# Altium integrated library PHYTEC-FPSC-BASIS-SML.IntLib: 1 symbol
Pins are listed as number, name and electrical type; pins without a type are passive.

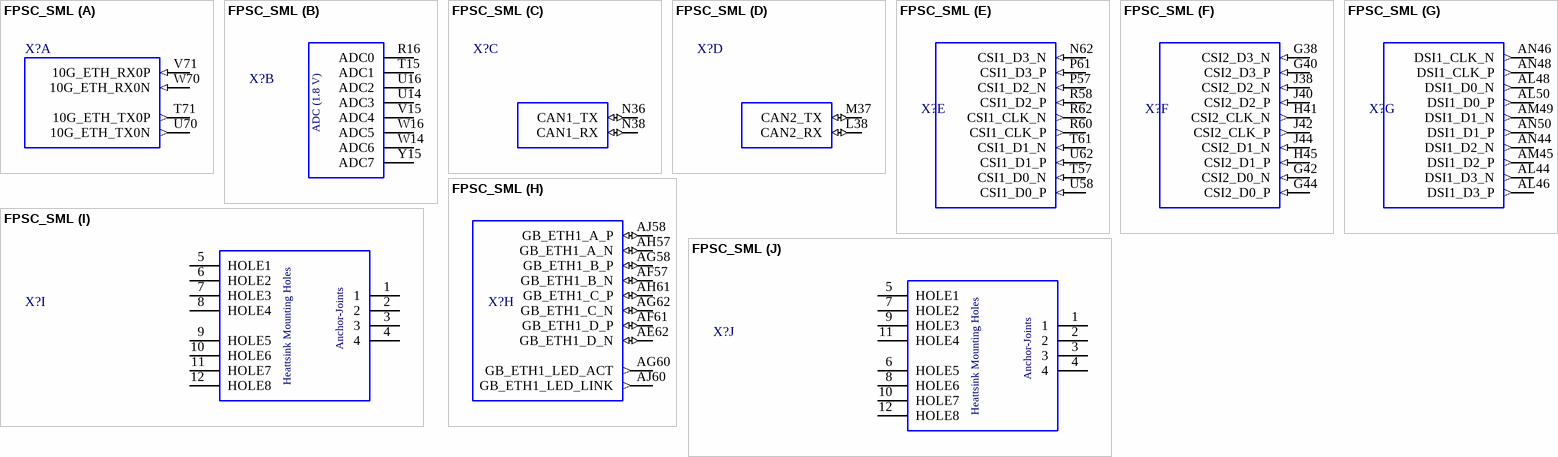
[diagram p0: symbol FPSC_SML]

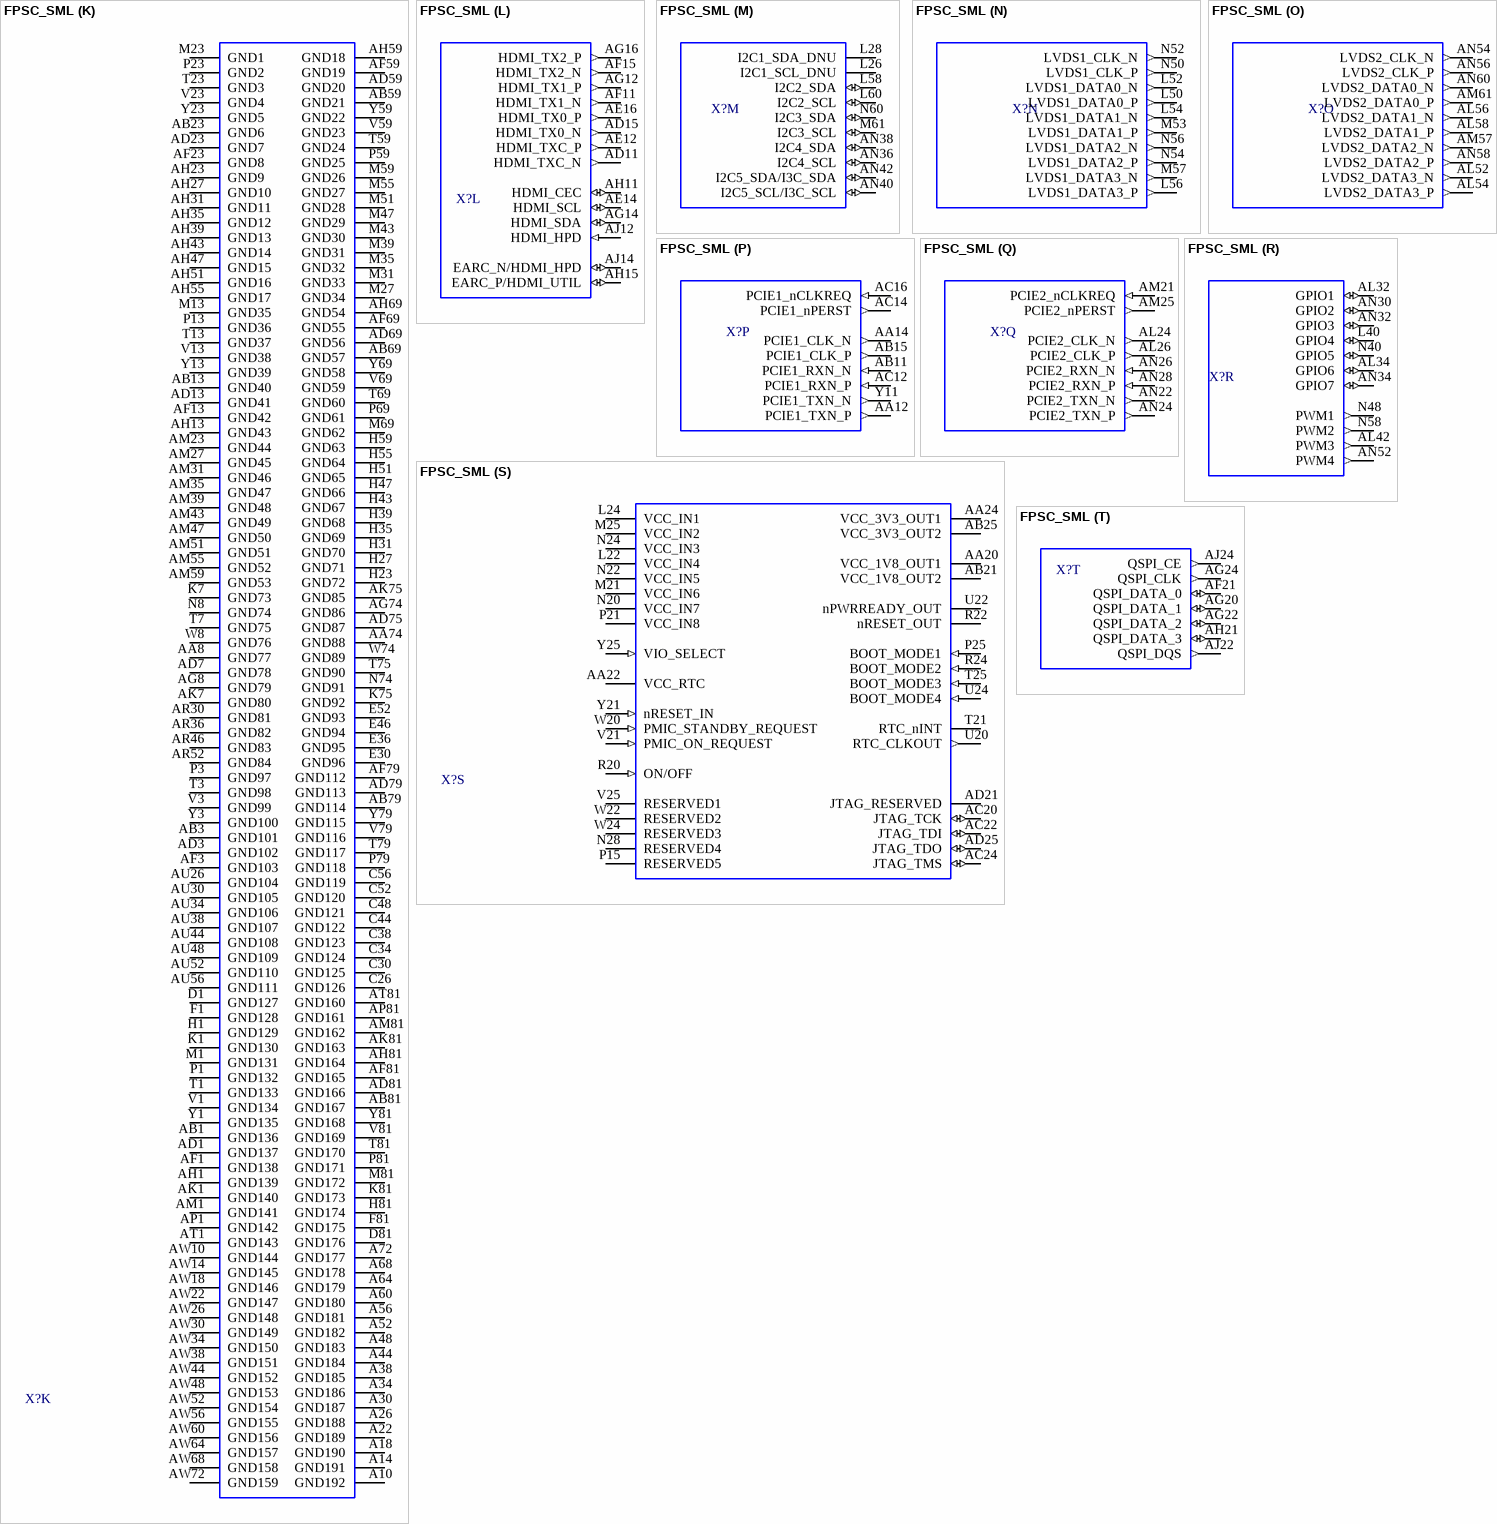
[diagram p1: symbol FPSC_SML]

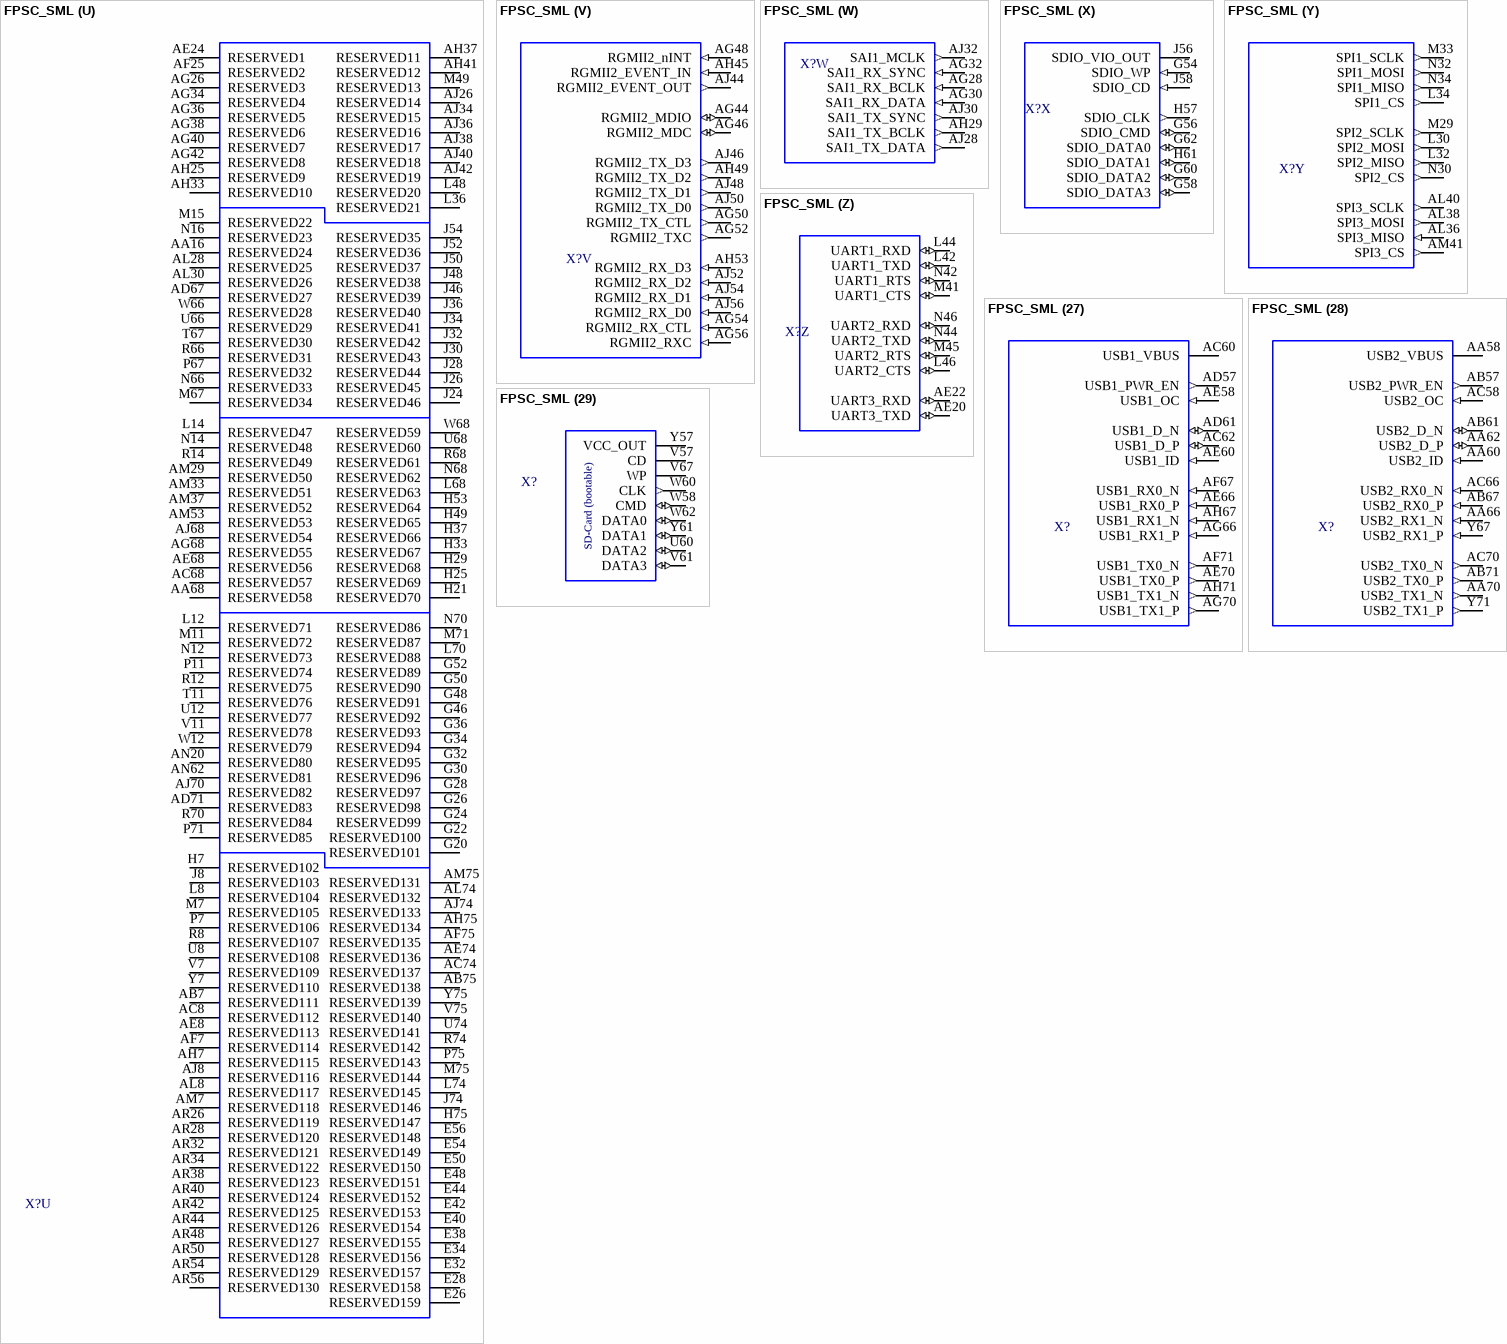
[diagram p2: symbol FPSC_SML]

## FPSC_SML
designator X?
footprint PHYTEC-FPSC-BASIS-SML (FPSC Basis für alle Varianten S,M und L)
part A pins: T71 10G_ETH_TX0P (out), U70 10G_ETH_TX0N (out), V71 10G_ETH_RX0P (in), W70 10G_ETH_RX0N (in)
part B pins: R16 ADC0, T15 ADC1, U14 ADC3, U16 ADC2, V15 ADC4, W14 ADC6, W16 ADC5, Y15 ADC7
part C pins: N36 CAN1_TX (io), N38 CAN1_RX (io)
part D pins: L38 CAN2_RX (io), M37 CAN2_TX (io)
part E pins: N62 CSI1_D3_N (in), P57 CSI1_D2_N (in), P61 CSI1_D3_P (in), R58 CSI1_D2_P (in), R60 CSI1_CLK_P (out), R62 CSI1_CLK_N (out), T57 CSI1_D0_N (in), T61 CSI1_D1_N (in), U58 CSI1_D0_P (in), U62 CSI1_D1_P (in)
part F pins: G38 CSI2_D3_N (in), G40 CSI2_D3_P (in), G42 CSI2_D0_N (in), G44 CSI2_D0_P (in), H41 CSI2_CLK_N (out), H45 CSI2_D1_P (in), J38 CSI2_D2_N (in), J40 CSI2_D2_P (in), J42 CSI2_CLK_P (out), J44 CSI2_D1_N (in)
part G pins: AL44 DSI1_D3_N (out), AL46 DSI1_D3_P (out), AL48 DSI1_D0_N (out), AL50 DSI1_D0_P (out), AM45 DSI1_D2_P (out), AM49 DSI1_D1_N (out), AN44 DSI1_D2_N (out), AN46 DSI1_CLK_N (out), AN48 DSI1_CLK_P (out), AN50 DSI1_D1_P (out)
part H pins: AE62 GB_ETH1_D_N (io), AF57 GB_ETH1_B_N (io), AF61 GB_ETH1_D_P (io), AG58 GB_ETH1_B_P (io), AG60 GB_ETH1_LED_ACT (out), AG62 GB_ETH1_C_N (io), AH57 GB_ETH1_A_N (io), AH61 GB_ETH1_C_P (io), AJ58 GB_ETH1_A_P (io), AJ60 GB_ETH1_LED_LINK (out)
part I pins: 1 (power), 2 (power), 3 (power), 4 (power), 5 HOLE1 (power), 6 HOLE2 (power), 7 HOLE3 (power), 8 HOLE4 (power), 9 HOLE5 (power), 10 HOLE6 (power), 11 HOLE7 (power), 12 HOLE8 (power)
part J pins: 1 (power), 2 (power), 3 (power), 4 (power), 5 HOLE1 (power), 6 HOLE5 (power), 7 HOLE2 (power), 8 HOLE6 (power), 9 HOLE3 (power), 10 HOLE7 (power), 11 HOLE4 (power), 12 HOLE8 (power)
part K pins: A10 GND192 (power), A14 GND191 (power), A18 GND190 (power), A22 GND189 (power), A26 GND188 (power), A30 GND187 (power), A34 GND186 (power), A38 GND185 (power), A44 GND184 (power), A48 GND183 (power), A52 GND182 (power), A56 GND181 (power), A60 GND180 (power), A64 GND179 (power), A68 GND178 (power), A72 GND177 (power), AA8 GND77 (power), AA74 GND88 (power), AB1 GND136 (power), AB3 GND101 (power), AB13 GND40 (power), AB23 GND6 (power), AB59 GND21 (power), AB69 GND57 (power), AB79 GND114 (power), AB81 GND167 (power), AD1 GND137 (power), AD3 GND102 (power), AD7 GND78 (power), AD13 GND41 (power), AD23 GND7 (power), AD59 GND20 (power), AD69 GND56 (power), AD75 GND87 (power), AD79 GND113 (power), AD81 GND166 (power), AF1 GND138 (power), AF3 GND103 (power), AF13 GND42 (power), AF23 GND8 (power), AF59 GND19 (power), AF69 GND55 (power), AF79 GND112 (power), AF81 GND165 (power), AG8 GND79 (power), AG74 GND86 (power), AH1 GND139 (power), AH13 GND43 (power), AH23 GND9 (power), AH27 GND10 (power), AH31 GND11 (power), AH35 GND12 (power), AH39 GND13 (power), AH43 GND14 (power), AH47 GND15 (power), AH51 GND16 (power), AH55 GND17 (power), AH59 GND18 (power), AH69 GND54 (power), AH81 GND164 (power), AK1 GND140 (power), AK7 GND80 (power), AK75 GND85 (power), AK81 GND163 (power), AM1 GND141 (power), AM23 GND44 (power), AM27 GND45 (power), AM31 GND46 (power), AM35 GND47 (power), AM39 GND48 (power), AM43 GND49 (power), AM47 GND50 (power), AM51 GND51 (power), AM55 GND52 (power), AM59 GND53 (power), AM81 GND162 (power), AP1 GND142 (power), AP81 GND161 (power), AR30 GND81 (power), AR36 GND82 (power), AR46 GND83 (power), AR52 GND84 (power), AT1 GND143 (power), AT81 GND160 (power), AU26 GND104 (power), AU30 GND105 (power), AU34 GND106 (power), AU38 GND107 (power), AU44 GND108 (power), AU48 GND109 (power), AU52 GND110 (power), AU56 GND111 (power), AW10 GND144 (power), AW14 GND145 (power), AW18 GND146 (power), AW22 GND147 (power), AW26 GND148 (power), AW30 GND149 (power), AW34 GND150 (power), AW38 GND151 (power), AW44 GND152 (power), AW48 GND153 (power), AW52 GND154 (power), AW56 GND155 (power), AW60 GND156 (power), AW64 GND157 (power), AW68 GND158 (power), AW72 GND159 (power), C26 GND126 (power), C30 GND125 (power), C34 GND124 (power), C38 GND123 (power), C44 GND122 (power), C48 GND121 (power), C52 GND120 (power), C56 GND119 (power), D1 GND127 (power), D81 GND176 (power), E30 GND96 (power), E36 GND95 (power), E46 GND94 (power), E52 GND93 (power), F1 GND128 (power), F81 GND175 (power), H1 GND129 (power), H23 GND72 (power), H27 GND71 (power), H31 GND70 (power), H35 GND69 (power), H39 GND68 (power), H43 GND67 (power), H47 GND66 (power), H51 GND65 (power), H55 GND64 (power), H59 GND63 (power), H81 GND174 (power), K1 GND130 (power), K7 GND73 (power), K75 GND92 (power), K81 GND173 (power), M1 GND131 (power), M13 GND35 (power), M23 GND1 (power), M27 GND34 (power), M31 GND33 (power), M35 GND32 (power), M39 GND31 (power), M43 GND30 (power), M47 GND29 (power), M51 GND28 (power), M55 GND27 (power), M59 GND26 (power), M69 GND62 (power), M81 GND172 (power), N8 GND74 (power), N74 GND91 (power), P1 GND132 (power), P3 GND97 (power), P13 GND36 (power), P23 GND2 (power), P59 GND25 (power), P69 GND61 (power), P79 GND118 (power), P81 GND171 (power), T1 GND133 (power), T3 GND98 (power), T7 GND75 (power), T13 GND37 (power), T23 GND3 (power), T59 GND24 (power), T69 GND60 (power), T75 GND90 (power), T79 GND117 (power), T81 GND170 (power), V1 GND134 (power), V3 GND99 (power), V13 GND38 (power), V23 GND4 (power), V59 GND23 (power), V69 GND59 (power), V79 GND116 (power), V81 GND169 (power), W8 GND76 (power), W74 GND89 (power), Y1 GND135 (power), Y3 GND100 (power), Y13 GND39 (power), Y23 GND5 (power), Y59 GND22 (power), Y69 GND58 (power), Y79 GND115 (power), Y81 GND168 (power)
part L pins: AD11 HDMI_TXC_N (out), AD15 HDMI_TX0_N (out), AE12 HDMI_TXC_P (out), AE14 HDMI_SCL (io), AE16 HDMI_TX0_P (out), AF11 HDMI_TX1_N (out), AF15 HDMI_TX2_N (out), AG12 HDMI_TX1_P (out), AG14 HDMI_SDA (io), AG16 HDMI_TX2_P (out), AH11 HDMI_CEC (io), AH15 EARC_P/HDMI_UTIL (io), AJ12 HDMI_HPD (in), AJ14 EARC_N/HDMI_HPD (io)
part M pins: AN36 I2C4_SCL (io), AN38 I2C4_SDA (io), AN40 I2C5_SCL/I3C_SCL (io), AN42 I2C5_SDA/I3C_SDA (io), L26 I2C1_SCL_DNU (oc), L28 I2C1_SDA_DNU (oc), L58 I2C2_SDA (io), L60 I2C2_SCL (io), M61 I2C3_SCL (io), N60 I2C3_SDA (io)
part N pins: L50 LVDS1_DATA0_P (out), L52 LVDS1_DATA0_N (out), L54 LVDS1_DATA1_N (out), L56 LVDS1_DATA3_P (out), M53 LVDS1_DATA1_P (out), M57 LVDS1_DATA3_N (out), N50 LVDS1_CLK_P (out), N52 LVDS1_CLK_N (out), N54 LVDS1_DATA2_P (out), N56 LVDS1_DATA2_N (out)
part O pins: AL52 LVDS2_DATA3_N (out), AL54 LVDS2_DATA3_P (out), AL56 LVDS2_DATA1_N (out), AL58 LVDS2_DATA1_P (out), AM57 LVDS2_DATA2_N (out), AM61 LVDS2_DATA0_P (out), AN54 LVDS2_CLK_N (out), AN56 LVDS2_CLK_P (out), AN58 LVDS2_DATA2_P (out), AN60 LVDS2_DATA0_N (out)
part P pins: AA12 PCIE1_TXN_P (out), AA14 PCIE1_CLK_N (out), AB11 PCIE1_RXN_N (in), AB15 PCIE1_CLK_P (out), AC12 PCIE1_RXN_P (in), AC14 PCIE1_nPERST (out), AC16 PCIE1_nCLKREQ (in), Y11 PCIE1_TXN_N (out)
part Q pins: AL24 PCIE2_CLK_N (out), AL26 PCIE2_CLK_P (out), AM21 PCIE2_nCLKREQ (in), AM25 PCIE2_nPERST (out), AN22 PCIE2_TXN_N (out), AN24 PCIE2_TXN_P (out), AN26 PCIE2_RXN_N (in), AN28 PCIE2_RXN_P (in)
part R pins: AL32 GPIO1 (io), AL34 GPIO6 (io), AL42 PWM3 (out), AN30 GPIO2 (io), AN32 GPIO3 (io), AN34 GPIO7 (io), AN52 PWM4 (out), L40 GPIO4 (io), N40 GPIO5 (io), N48 PWM1 (out), N58 PWM2 (out)
part S pins: AA20 VCC_1V8_OUT1 (power), AA22 VCC_RTC (power), AA24 VCC_3V3_OUT1 (power), AB21 VCC_1V8_OUT2 (power), AB25 VCC_3V3_OUT2 (power), AC20 JTAG_TCK (io), AC22 JTAG_TDI (io), AC24 JTAG_TMS (io), AD21 JTAG_RESERVED, AD25 JTAG_TDO (io), L22 VCC_IN4 (power), L24 VCC_IN1 (power), M21 VCC_IN6 (power), M25 VCC_IN2 (power), N20 VCC_IN7 (power), N22 VCC_IN5 (power), N24 VCC_IN3 (power), N28 RESERVED4, P15 RESERVED5, P21 VCC_IN8 (power), P25 BOOT_MODE1 (in), R20 ON/OFF (in), R22 nRESET_OUT (oc), R24 BOOT_MODE2 (in), T21 RTC_nINT (oc), T25 BOOT_MODE3 (in), U20 RTC_CLKOUT (out), U22 nPWRREADY_OUT (oc), U24 BOOT_MODE4 (in), V21 PMIC_ON_REQUEST (in), V25 RESERVED1, W20 PMIC_STANDBY_REQUEST (in), W22 RESERVED2, W24 RESERVED3, Y21 nRESET_IN (in), Y25 VIO_SELECT (in)
part T pins: AF21 QSPI_DATA_0 (io), AG20 QSPI_DATA_1 (io), AG22 QSPI_DATA_2 (io), AG24 QSPI_CLK (out), AH21 QSPI_DATA_3 (io), AJ22 QSPI_DQS (out), AJ24 QSPI_CE (out)
part U pins: AA16 RESERVED24, AA68 RESERVED58, AB7 RESERVED111, AB75 RESERVED138, AC8 RESERVED112, AC68 RESERVED57, AC74 RESERVED137, AD67 RESERVED27, AD71 RESERVED83, AE8 RESERVED113, AE24 RESERVED1, AE68 RESERVED56, AE74 RESERVED136, AF7 RESERVED114, AF25 RESERVED2, AF75 RESERVED135, AG26 RESERVED3, AG34 RESERVED4, AG36 RESERVED5, AG38 RESERVED6, AG40 RESERVED7, AG42 RESERVED8, AG68 RESERVED55, AH7 RESERVED115, AH25 RESERVED9, AH33 RESERVED10, AH37 RESERVED11, AH41 RESERVED12, AH75 RESERVED134, AJ8 RESERVED116, AJ26 RESERVED14, AJ34 RESERVED15, AJ36 RESERVED16, AJ38 RESERVED17, AJ40 RESERVED18, AJ42 RESERVED19, AJ68 RESERVED54, AJ70 RESERVED82, AJ74 RESERVED133, AL8 RESERVED117, AL28 RESERVED25, AL30 RESERVED26, AL74 RESERVED132, AM7 RESERVED118, AM29 RESERVED50, AM33 RESERVED51, AM37 RESERVED52, AM53 RESERVED53, AM75 RESERVED131, AN20 RESERVED80, AN62 RESERVED81, AR26 RESERVED119, AR28 RESERVED120, AR32 RESERVED121, AR34 RESERVED122, AR38 RESERVED123, AR40 RESERVED124, AR42 RESERVED125, AR44 RESERVED126, AR48 RESERVED127, AR50 RESERVED128, AR54 RESERVED129, AR56 RESERVED130, E26 RESERVED159, E28 RESERVED158, E32 RESERVED157, E34 RESERVED156, E38 RESERVED155, E40 RESERVED154, E42 RESERVED153, E44 RESERVED152, E48 RESERVED151, E50 RESERVED150, E54 RESERVED149, E56 RESERVED148, G20 RESERVED101, G22 RESERVED100, G24 RESERVED99, G26 RESERVED98, G28 RESERVED97, G30 RESERVED96, G32 RESERVED95, G34 RESERVED94, G36 RESERVED93, G46 RESERVED92, G48 RESERVED91, G50 RESERVED90, G52 RESERVED89, H7 RESERVED102, H21 RESERVED70, H25 RESERVED69, H29 RESERVED68, H33 RESERVED67, H37 RESERVED66, H49 RESERVED65, H53 RESERVED64, H75 RESERVED147, J8 RESERVED103, J24 RESERVED46, J26 RESERVED45, J28 RESERVED44, J30 RESERVED43, J32 RESERVED42, J34 RESERVED41, J36 RESERVED40, J46 RESERVED39, J48 RESERVED38, J50 RESERVED37, J52 RESERVED36, J54 RESERVED35, J74 RESERVED146, L8 RESERVED104, L12 RESERVED71, L14 RESERVED47, L36 RESERVED21, L48 RESERVED20, L68 RESERVED63, L70 RESERVED88, L74 RESERVED145, M7 RESERVED105, M11 RESERVED72, M15 RESERVED22, M49 RESERVED13, M67 RESERVED34, M71 RESERVED87, M75 RESERVED144, N12 RESERVED73, N14 RESERVED48, N16 RESERVED23, N66 RESERVED33, N68 RESERVED62, N70 RESERVED86, P7 RESERVED106, P11 RESERVED74, P67 RESERVED32, P71 RESERVED85, P75 RESERVED143, R8 RESERVED107, R12 RESERVED75, R14 RESERVED49, R66 RESERVED31, R68 RESERVED61, R70 RESERVED84, R74 RESERVED142, T11 RESERVED76, T67 RESERVED30, U8 RESERVED108, U12 RESERVED77, U66 RESERVED29, U68 RESERVED60, U74 RESERVED141, V7 RESERVED109, V11 RESERVED78, V75 RESERVED140, W12 RESERVED79, W66 RESERVED28, W68 RESERVED59, Y7 RESERVED110, Y75 RESERVED139
part V pins: AG44 RGMII2_MDIO (io), AG46 RGMII2_MDC (io), AG48 RGMII2_nINT (in), AG50 RGMII2_TX_CTL (out), AG52 RGMII2_TXC (out), AG54 RGMII2_RX_CTL (in), AG56 RGMII2_RXC (in), AH45 RGMII2_EVENT_IN (in), AH49 RGMII2_TX_D2 (out), AH53 RGMII2_RX_D3 (in), AJ44 RGMII2_EVENT_OUT (out), AJ46 RGMII2_TX_D3 (out), AJ48 RGMII2_TX_D1 (out), AJ50 RGMII2_TX_D0 (out), AJ52 RGMII2_RX_D2 (in), AJ54 RGMII2_RX_D1 (in), AJ56 RGMII2_RX_D0 (in)
part W pins: AG28 SAI1_RX_BCLK (in), AG30 SAI1_RX_DATA (in), AG32 SAI1_RX_SYNC (in), AH29 SAI1_TX_BCLK (out), AJ28 SAI1_TX_DATA (out), AJ30 SAI1_TX_SYNC (out), AJ32 SAI1_MCLK (out)
part X pins: G54 SDIO_WP (in), G56 SDIO_CMD (io), G58 SDIO_DATA3 (io), G60 SDIO_DATA2 (io), G62 SDIO_DATA0 (io), H57 SDIO_CLK (out), H61 SDIO_DATA1 (io), J56 SDIO_VIO_OUT (power), J58 SDIO_CD (in)
part Y pins: AL36 SPI3_MISO (in), AL38 SPI3_MOSI (out), AL40 SPI3_SCLK (out), AM41 SPI3_CS (out), L30 SPI2_MOSI (out), L32 SPI2_MISO (out), L34 SPI1_CS (out), M29 SPI2_SCLK (out), M33 SPI1_SCLK (out), N30 SPI2_CS (out), N32 SPI1_MOSI (out), N34 SPI1_MISO (out)
part Z pins: AE20 UART3_TXD (io), AE22 UART3_RXD (io), L42 UART1_TXD (io), L44 UART1_RXD (io), L46 UART2_CTS (io), M41 UART1_CTS (io), M45 UART2_RTS (io), N42 UART1_RTS (io), N44 UART2_TXD (io), N46 UART2_RXD (io)
part 27 pins: AC60 USB1_VBUS (power), AC62 USB1_D_P (io), AD57 USB1_PWR_EN (out), AD61 USB1_D_N (io), AE58 USB1_OC (in), AE60 USB1_ID (in), AE66 USB1_RX0_P (in), AE70 USB1_TX0_P (out), AF67 USB1_RX0_N (in), AF71 USB1_TX0_N (out), AG66 USB1_RX1_P (in), AG70 USB1_TX1_P (out), AH67 USB1_RX1_N (in), AH71 USB1_TX1_N (out)
part 28 pins: AA58 USB2_VBUS (power), AA60 USB2_ID (in), AA62 USB2_D_P (io), AA66 USB2_RX1_N (in), AA70 USB2_TX1_N (out), AB57 USB2_PWR_EN (out), AB61 USB2_D_N (io), AB67 USB2_RX0_P (in), AB71 USB2_TX0_P (out), AC58 USB2_OC (in), AC66 USB2_RX0_N (in), AC70 USB2_TX0_N (out), Y67 USB2_RX1_P (in), Y71 USB2_TX1_P (out)
part 29 pins: U60 DATA2 (io), V57 CD (oc), V61 DATA3 (io), V67 WP (oc), W58 CMD (io), W60 CLK (out), W62 DATA0 (io), Y57 VCC_OUT (power), Y61 DATA1 (io)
